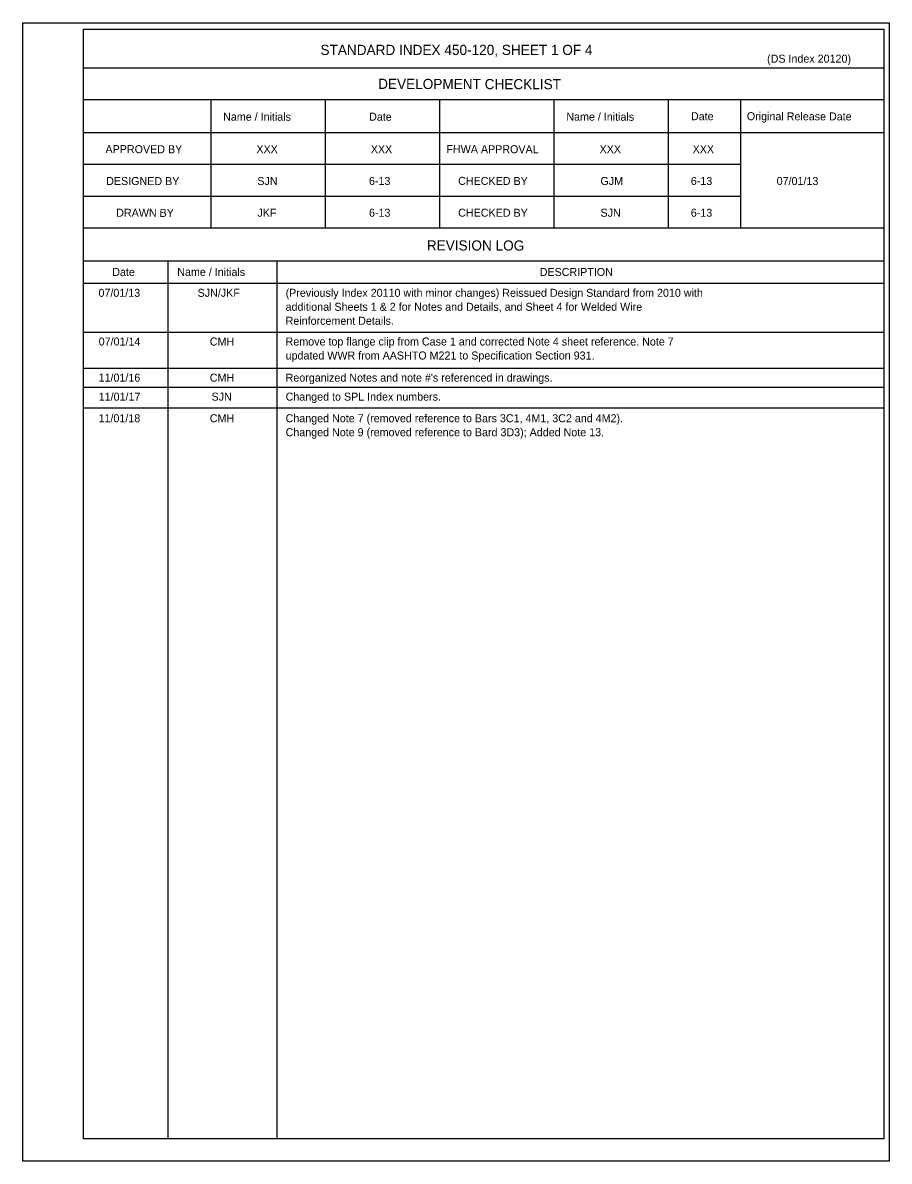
# Model space of a CAD drawing. Extents: x -119 to 80, y -12 to 144.
# Drawn here: x 25.69 to 42.05, y 38.14 to 59.64 of the extents above; entities that cross this region are included whole.
import ezdxf

# ---------------------------------------------------------------- set-up
doc = ezdxf.new("R2010")
doc.units = 0
for name, color, linetype in [('AdhocPoint_dp', 7, 'Continuous'), ('Border', 7, 'Continuous'), ('TextMisc', 7, 'Continuous')]:
    doc.layers.add(name, color=color, linetype=linetype)

msp = doc.modelspace()

# ---------------------------------------------------------------- linework, layer by layer
at = {"layer": 'AdhocPoint_dp'}
for p, q in [((26.837, 53.796), (41.947, 53.796)), ((26.837, 53.115), (41.947, 53.115)), ((26.837, 52.756), (41.947, 52.756)), ((26.837, 52.369), (41.947, 52.369))]:
    msp.add_line(p, q, dxfattribs=at)
at = {"layer": 'Border'}
for p, q in [((41.947, 58.781), (26.837, 58.781)), ((41.947, 58.181), (26.837, 58.181)), ((29.237, 58.181), (29.237, 55.76)), ((31.397, 58.181), (31.397, 55.76)), ((33.557, 58.181), (33.557, 55.76)), ((35.717, 58.181), (35.717, 55.76)), ((37.877, 58.181), (37.877, 55.76)), ((39.238, 58.181), (39.238, 55.76)), ((41.947, 57.56), (26.837, 57.56)), ((39.238, 56.96), (26.837, 56.96)), ((39.238, 56.36), (26.837, 56.36)), ((41.947, 55.76), (26.837, 55.76)), ((41.947, 55.139), (26.837, 55.139)), ((28.427, 55.139), (28.427, 38.559)), ((30.484, 55.139), (30.484, 38.559)), ((41.947, 54.716), (26.837, 54.716)), ((25.689, 38.138), (25.689, 38.138))]:
    msp.add_line(p, q, dxfattribs=at)
for points in [[(25.689, 59.638), (42.049, 59.638), (42.049, 38.138), (25.689, 38.138)], [(26.837, 59.516), (41.947, 59.516), (41.947, 38.559), (26.837, 38.559)]]:
    msp.add_lwpolyline(points, close=True, dxfattribs=at)

# ---------------------------------------------------------------- texts
at = {"layer": 'TextMisc'}
for s, height, p in [('STANDARD INDEX 450-120, SHEET 1 OF 4', 0.192, (31.31, 59.03)), ('(DS Index 20120)', 0.1512, (39.743, 58.885)), ('XXX', 0.1512, (30.1, 57.175)), ('XXX', 0.1512, (32.26, 57.175)), ('XXX', 0.1512, (36.58, 57.175)), ('XXX', 0.1512, (38.337, 57.175)), ('SJN', 0.1512, (30.118, 56.575)), ('6-13', 0.1512, (32.226, 56.575)), ('GJM', 0.1512, (36.597, 56.575)), ('6-13', 0.1512, (38.303, 56.575)), ('07/01/13', 0.1512, (39.924, 56.575)), ('JKF', 0.1512, (30.12, 55.975)), ('6-13', 0.1512, (32.226, 55.975)), ('SJN', 0.1512, (36.598, 55.975)), ('6-13', 0.1512, (38.303, 55.975)), ('DESCRIPTION', 0.1512, (35.45, 54.856)), ('07/01/13', 0.1512, (27.119, 54.463)), ('SJN/JKF', 0.1512, (28.99, 54.463)), ('(Previously Index 20110 with minor changes) Reissued Design Standard from 2010 with', 0.1512, (30.652, 54.463)), ('additional Sheets 1 & 2 for Notes and Details, and Sheet 4 for Welded Wire', 0.1512, (30.652, 54.199)), ('Reinforcement Details. ', 0.1512, (30.652, 53.935)), ('07/01/14', 0.1512, (27.123, 53.543)), ('CMH', 0.1512, (29.221, 53.543)), ('Remove top flange clip from Case 1 and corrected Note 4 sheet reference. Note 7', 0.1512, (30.652, 53.543)), ('updated WWR from AASHTO M221 to Specification Section 931.', 0.1512, (30.652, 53.279)), ('11/01/16', 0.1512, (27.121, 52.861)), ('CMH', 0.1512, (29.221, 52.861)), ("Reorganized Notes and note #'s referenced in drawings.", 0.1512, (30.652, 52.861)), ('11/01/17', 0.1512, (27.123, 52.502)), ('SJN', 0.1512, (29.253, 52.502)), ('Changed to SPL Index numbers.', 0.1512, (30.652, 52.502)), ('11/01/18', 0.1512, (27.12, 52.094)), ('CMH', 0.1512, (29.221, 52.094)), ('Changed Note 7 (removed reference to Bars 3C1, 4M1, 3C2 and 4M2). ', 0.1512, (30.652, 52.094)), ('Changed Note 9 (removed reference to Bard 3D3); Added Note 13.', 0.1512, (30.652, 51.83))]:
    msp.add_text(s, height=height, dxfattribs=at).set_placement(p)
for s, height, p in [('DEVELOPMENT CHECKLIST', 0.192, (32.399, 58.389)), ('Name / Initials', 0.1512, (29.472, 57.79)), ('Date', 0.1512, (32.228, 57.789)), ('Name / Initials', 0.1512, (35.952, 57.79)), ('Date', 0.1512, (38.306, 57.798)), ('Original Release Date', 0.1512, (39.361, 57.798)), ('APPROVED BY', 0.1512, (27.251, 57.177)), ('FHWA APPROVAL', 0.1512, (33.688, 57.177)), ('DESIGNED BY', 0.1512, (27.264, 56.575)), ('CHECKED BY', 0.1512, (33.91, 56.577)), ('DRAWN BY', 0.1512, (27.453, 55.975)), ('CHECKED BY', 0.1512, (33.91, 55.977)), ('REVISION LOG', 0.192, (33.318, 55.339)), ('Date', 0.1512, (27.379, 54.857)), ('Name / Initials', 0.1512, (28.606, 54.858))]:
    msp.add_text(s, height=height, rotation=359.8756, dxfattribs=at).set_placement(p)

doc.saveas('drawing.dxf')
